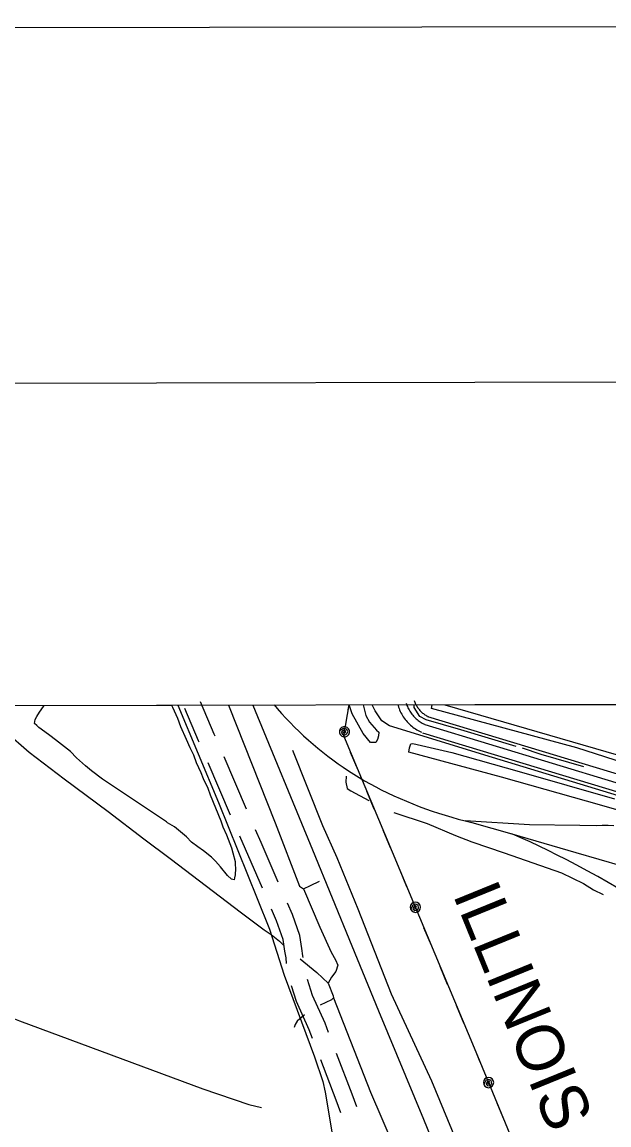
# Model space of a CAD drawing. Extents: x 3324104 to 3361979, y 612876 to 638273.
# Drawn here: x 3355510 to 3356542, y 635751 to 637690 of the extents above; entities that cross this region are included whole.
import ezdxf

# ---------------------------------------------------------------- set-up
doc = ezdxf.new("R2010")
doc.units = 0
for name, color, linetype in [('G-ANNO-NPLT', 7, 'Continuous'), ('V-ANNO-SYMB', 7, 'Continuous'), ('V-GRID-FRAM', 7, 'Continuous'), ('V-RAIL-IDEN', 7, 'Continuous'), ('V-RAIL-TRAK', 7, 'Continuous'), ('V-ROAD-CNTR', 7, 'Continuous'), ('V-SITE-OTLN', 7, 'Continuous'), ('V-SITE-VEGE', 7, 'Continuous'), ('V-TOPO-SHOR', 7, 'Continuous'), ('V-UTIL-LINE', 7, 'Continuous')]:
    doc.layers.add(name, color=color, linetype=linetype)

msp = doc.modelspace()

# ---------------------------------------------------------------- linework, layer by layer
at = {"layer": 'G-ANNO-NPLT'}
msp.add_lwpolyline([(3324729.4, 613459.1), (3361396, 613523.1), (3361353.8, 637689.8), (3324687.2, 637625.8)], close=True, dxfattribs=at)
at = {"layer": 'V-ANNO-SYMB'}
msp.add_lwpolyline([(3327478.4, 614089), (3360561.6, 614146.7), (3360521.6, 637063.3), (3327438.4, 637005.5), (3327478.4, 614089)], dxfattribs=at)
at = {"layer": 'V-GRID-FRAM'}
msp.add_lwpolyline([(3328194.1, 636440.7), (3359767.9, 636495.9), (3359807.6, 618312.1), (3328217.9, 618256.9), (3328194.1, 636440.7)], dxfattribs=at)
at = {"layer": 'V-RAIL-TRAK'}
for points in [[(3355915.7, 636489.1), (3356020.4, 636234.6), (3356089.6, 636065.9), (3356136.8, 635951.6), (3356215.6, 635761.2), (3356284.7, 635591.1)], [(3355953, 636489.2), (3355958.5, 636482.7), (3355965.9, 636474.4), (3355973.4, 636466.2), (3355981.1, 636458.2), (3355988.9, 636450.3), (3355996.8, 636442.5), (3356004.9, 636434.9), (3356013.2, 636427.4), (3356021.6, 636420.1), (3356030.1, 636413), (3356038.7, 636406), (3356047.5, 636399.1), (3356056.4, 636392.5), (3356065.4, 636385.9), (3356074.5, 636379.6), (3356083.8, 636373.4), (3356093.2, 636367.4), (3356102.6, 636361.6), (3356112.2, 636356), (3356121.9, 636350.5), (3356131.7, 636345.2), (3356141.5, 636340.1), (3356152.4, 636334.7), (3356163.3, 636329.6), (3356174.4, 636324.6), (3356185.5, 636319.8), (3356196.7, 636315.3), (3356207.9, 636310.9), (3356219.3, 636306.7), (3356230.7, 636302.7), (3356242.1, 636298.8), (3356253.7, 636295.2), (3356265.3, 636291.8), (3356276.9, 636288.6), (3356288.7, 636285.6), (3356300.4, 636282.7), (3356370.8, 636262.5), (3356483.7, 636230.1), (3356807.1, 636136.2)], [(3356550.7, 636276.9), (3356540.2, 636277.1), (3356529.7, 636277.1), (3356519.2, 636276.8), (3356490.7, 636277.2), (3356402.4, 636278.3), (3356288.7, 636285.6)], [(3356558.7, 636166.5), (3356540.5, 636177), (3356522.2, 636187.4), (3356503.7, 636197.5), (3356485.2, 636207.6), (3356466.6, 636217.4), (3356450.9, 636225.4), (3356435.1, 636233.3), (3356419.2, 636240.9), (3356403.1, 636248.3), (3356387, 636255.5), (3356370.8, 636262.5)]]:
    msp.add_lwpolyline(points, dxfattribs=at)
at = {"layer": 'V-ROAD-CNTR'}
for p, q in [((3355876.5, 636295.4), (3355836.9, 636387.2)), ((3355904.6, 636306.1), (3355865, 636397.9))]:
    msp.add_line(p, q, dxfattribs=at)
for points in [[(3355821.1, 636423.9), (3355820.1, 636426.3), (3355795.8, 636483)], [(3355849.1, 636434.6), (3355847.7, 636438.1), (3355823.4, 636494.8)], [(3356170.9, 636488), (3356171.7, 636485.6), (3356172.6, 636483), (3356173.7, 636480.5), (3356174.8, 636477.9), (3356176, 636475.5), (3356177.3, 636473.1), (3356178.7, 636470.7), (3356180.2, 636468.4), (3356181.8, 636466.1), (3356183.4, 636463.9), (3356185.2, 636461.7), (3356187, 636459.6), (3356188.9, 636457.6), (3356190.8, 636455.7), (3356192.8, 636453.8), (3356194.9, 636452), (3356197.1, 636450.3), (3356199.3, 636448.6), (3356201.5, 636447.1), (3356203.9, 636445.6), (3356206.2, 636444.2), (3356208.7, 636442.9), (3356211.1, 636441.7), (3356212, 636441.3)], [(3356185.1, 636492.6), (3356185.8, 636490.5), (3356186.6, 636488.4), (3356187.4, 636486.4), (3356188.4, 636484.4), (3356189.3, 636482.4), (3356190.4, 636480.4), (3356191.5, 636478.5), (3356192.7, 636476.7), (3356194, 636474.8), (3356195.3, 636473.1), (3356196.7, 636471.3), (3356198.1, 636469.7), (3356199.6, 636468), (3356201.2, 636466.5), (3356202.8, 636465), (3356204.5, 636463.5), (3356206.2, 636462.1), (3356208, 636460.8), (3356209.8, 636459.6), (3356211.7, 636458.4), (3356213.6, 636457.2), (3356215.6, 636456.2), (3356217.6, 636455.2), (3356218.3, 636454.8)], [(3356199.4, 636497.3), (3356200, 636495.4), (3356200.6, 636493.9), (3356201.2, 636492.3), (3356201.9, 636490.8), (3356202.7, 636489.3), (3356203.4, 636487.8), (3356204.3, 636486.4), (3356205.2, 636485), (3356206.2, 636483.6), (3356207.2, 636482.3), (3356208.2, 636481), (3356209.3, 636479.7), (3356210.4, 636478.5), (3356211.6, 636477.3), (3356212.9, 636476.1), (3356214.1, 636475), (3356215.4, 636474), (3356216.8, 636473), (3356218.1, 636472), (3356219.6, 636471.1), (3356221, 636470.3), (3356222.5, 636469.5), (3356224, 636468.7), (3356224.6, 636468.4)], [(3356222.7, 636469.2), (3356670.5, 636333.3), (3357164.2, 636184.8)], [(3356218.3, 636454.8), (3356666.2, 636319), (3357159.9, 636170.5)], [(3356213.9, 636440.5), (3356661.8, 636304.6), (3357155.6, 636156.1)], [(3355960.3, 636177.7), (3355929.9, 636247.3), (3355920.4, 636269.4)], [(3355932.3, 636167), (3355902.4, 636235.4), (3355892.4, 636258.7)], [(3356003.9, 636045.5), (3356003.6, 636048.4), (3356001.6, 636061.3), (3355998.1, 636084.1), (3355985.2, 636120.6), (3355976.3, 636141)], [(3355974.9, 636034.6), (3355973.9, 636044.6), (3355971.9, 636056.6), (3355968.9, 636076.8), (3355957.3, 636109.6), (3355948.3, 636130.3)], [(3356048.6, 635913.6), (3356042.5, 635929.6), (3356020.3, 635978.3), (3356011.9, 636006.4)], [(3356020.6, 635902.9), (3356014.8, 635918), (3355992.1, 635967.8), (3355983.8, 635995.7)], [(3356070.3, 635772), (3356062.1, 635794.4), (3356034.9, 635865.6)], [(3356098.3, 635782.7), (3356090.2, 635804.9), (3356062.9, 635876.3)]]:
    msp.add_lwpolyline(points, dxfattribs=at)
at = {"layer": 'V-SITE-OTLN'}
for p, q in [((3356125.6, 636489.5), (3357284.2, 636491.5)), ((3356130.8, 636478.7), (3356125.6, 636489.5)), ((3356142.6, 636461.2), (3356130.8, 636478.7)), ((3356155.8, 636452.8), (3356142.6, 636461.2)), ((3356337.3, 636396.6), (3356155.8, 636452.8)), ((3356667.1, 636296.2), (3356337.3, 636396.6))]:
    msp.add_line(p, q, dxfattribs=at)
at = {"layer": 'V-SITE-VEGE'}
for p, q in [((3355543.1, 636480.9), (3355548.3, 636488.1)), ((3355548.3, 636488.1), (3355548.6, 636488.5)), ((3355548.6, 636488.5), (3355772.7, 636488.9)), ((3355772.7, 636488.9), (3355774.2, 636485.1)), ((3355774.2, 636485.1), (3355782.9, 636466)), ((3355531.6, 636456.7), (3355532.6, 636463.9)), ((3355532.6, 636463.9), (3355535.8, 636469.1)), ((3355535.8, 636469.1), (3355540.5, 636476.3)), ((3355540.5, 636476.3), (3355543.1, 636480.9)), ((3355782.9, 636466), (3355788.5, 636451.5)), ((3355535.7, 636453.1), (3355531.6, 636456.7)), ((3355539.3, 636449.4), (3355535.7, 636453.1)), ((3355549.6, 636442.1), (3355539.3, 636449.4)), ((3355788.5, 636451.5), (3355798.1, 636429.2)), ((3355558.3, 636435.3), (3355549.6, 636442.1)), ((3355568.6, 636428), (3355558.3, 636435.3)), ((3355594.8, 636407.2), (3355568.6, 636428)), ((3355798.1, 636429.2), (3355804.8, 636414.6)), ((3355605.6, 636396.3), (3355594.8, 636407.2)), ((3355804.8, 636414.6), (3355810.9, 636401.7)), ((3355621, 636382.2), (3355605.6, 636396.3)), ((3355810.9, 636401.7), (3355816, 636388.2)), ((3355816, 636388.2), (3355824.1, 636370.6)), ((3355631.8, 636373.4), (3355621, 636382.2)), ((3355650.9, 636358.8), (3355631.8, 636373.4)), ((3355824.1, 636370.6), (3355828.2, 636360.2)), ((3355763.6, 636283.6), (3355650.9, 636358.8)), ((3355828.2, 636360.2), (3355836.4, 636343.1)), ((3355836.4, 636343.1), (3355840.4, 636331.2)), ((3355840.4, 636331.2), (3355859.2, 636285.6)), ((3355765.7, 636282), (3355763.6, 636283.6)), ((3355777.5, 636274.7), (3355765.7, 636282)), ((3355781.1, 636272.1), (3355777.5, 636274.7)), ((3355798.6, 636257.5), (3355781.1, 636272.1)), ((3355859.2, 636285.6), (3355862.8, 636274.7)), ((3355862.8, 636274.7), (3355869.4, 636260.7)), ((3355807.8, 636248.2), (3355798.6, 636257.5)), ((3355869.4, 636260.7), (3355878.1, 636237.9)), ((3355818.6, 636239.8), (3355807.8, 636248.2)), ((3355828.9, 636232.5), (3355818.6, 636239.8)), ((3355842.8, 636221.6), (3355828.9, 636232.5)), ((3355878.1, 636237.9), (3355880.6, 636229.1)), ((3355850, 636214.8), (3355842.8, 636221.6)), ((3355858.7, 636204.4), (3355850, 636214.8)), ((3355880.6, 636229.1), (3355884.6, 636214.1)), ((3355884.6, 636214.1), (3355884.6, 636208.9)), ((3355871, 636189.3), (3355858.7, 636204.4)), ((3355885.1, 636201.7), (3355884.5, 636190.3)), ((3355884.6, 636208.9), (3355885.1, 636201.7)), ((3355878.2, 636183.1), (3355871, 636189.3)), ((3355882.9, 636181.5), (3355878.2, 636183.1)), ((3355883.4, 636185.1), (3355882.9, 636181.5)), ((3355884.5, 636190.3), (3355883.4, 636185.1))]:
    msp.add_line(p, q, dxfattribs=at)
at = {"layer": 'V-TOPO-SHOR'}
msp.add_line((3356120.5, 636458.9), (3356133, 636444.9), dxfattribs=at)
for points in [[(3355872.5, 636489.1), (3355954.5, 636282.1), (3355997.7, 636170.5), (3356004.6, 636166.2), (3356017.1, 636171.7), (3356032.5, 636179.3)], [(3356133, 636444.9), (3356137.1, 636441.4), (3356136.4, 636435.2), (3356135, 636428.2), (3356132.1, 636423.4), (3356130.1, 636423.4), (3356122.4, 636423.4), (3356109.3, 636438.8), (3356090, 636473.7), (3356084.8, 636489.4)], [(3356109.5, 636489.5), (3356114.4, 636470.8), (3356120.5, 636458.9)], [(3356378.6, 636415.9), (3356281.4, 636445.7), (3356220.3, 636462.8), (3356209.2, 636469.1), (3356199.5, 636484.5), (3356199.1, 636489.6)], [(3355480.7, 636442.4), (3355522.3, 636406.5), (3355583.8, 636359.2), (3355660.9, 636301.8), (3355723.8, 636253.7), (3355770.4, 636219.2)], [(3355985.3, 636409.9), (3356038, 636277.3), (3356063.4, 636220.8), (3356100.4, 636130.8), (3356158.6, 635981.6), (3356230, 635828.7), (3356271.7, 635726.2), (3356348.5, 635542), (3356409.4, 635388.5), (3356468.4, 635253.9), (3356519.8, 635119.9), (3356562.2, 635018.1), (3356611.6, 634907.1), (3356648.7, 634809.9)], [(3356617, 636302.7), (3356637.2, 636297), (3356646.2, 636292.8), (3356651.7, 636288.5), (3356651.7, 636284.4), (3356651.7, 636280.9), (3356646.8, 636279.5), (3356628.7, 636282.4), (3356608.6, 636289.5), (3356529.4, 636312.3), (3356353, 636362.1), (3356189.8, 636406.3), (3356191.2, 636413.9), (3356193.4, 636420.9), (3356196.8, 636421.6), (3356265.6, 636405.8), (3356383.7, 636372.4), (3356551.8, 636324)], [(3356497.4, 636380.3), (3356422.4, 636402.4), (3356389.7, 636413)], [(3356079.6, 636364.1), (3356078.8, 636353.6), (3356081.6, 636342.5), (3356087.8, 636338.3), (3356119.7, 636321.4)], [(3356163.4, 636300.2), (3356222.4, 636281), (3356271.7, 636259.9), (3356300.8, 636248.5), (3356357.8, 636229.4), (3356458.4, 636193.9), (3356497.3, 636175.6), (3356514.6, 636164.4), (3356531.9, 636155.9)], [(3355770.4, 636219.2), (3355895.8, 636123.8), (3355935.2, 636093.6), (3355947.7, 636085.9), (3355962.2, 636074), (3355969.9, 636066.3)], [(3356004.6, 636166.2), (3356033.4, 636098.6), (3356053.3, 636054.6), (3356060.8, 636041.3), (3356065, 636031.6), (3356061.4, 636020.4), (3356053.7, 636010.8), (3356048.1, 636000.4)], [(3355998.9, 636043.1), (3356028, 636018.6), (3356048.1, 636000.4), (3356057, 635978), (3356057.6, 635974.6), (3356054.1, 635971.1), (3356033.9, 635961.5)], [(3356057.6, 635974.6), (3356122.7, 635808.5), (3356185.7, 635661.3), (3356166.2, 635651)], [(3355306.2, 635541.5), (3355270.1, 635565.3), (3355271.6, 635572.4), (3355273.8, 635578.7), (3355290.3, 635599.2), (3355293.9, 635614.8), (3355309.8, 635649.5), (3355319.9, 635672.9), (3355324.3, 635687.8), (3355330.3, 635724.7), (3355341.2, 635768), (3355347.8, 635787.2), (3355359.2, 635801.3), (3355402.4, 635869.9), (3355449.8, 635942.1), (3355456.3, 635947.7), (3355466.2, 635949.1), (3355505.2, 635933.8), (3355630, 635887.4), (3355827.7, 635814.2), (3355908.6, 635786.6), (3355930.5, 635781.5)], [(3356006.6, 635944.3), (3355993.4, 635933.2), (3355989.8, 635927.7), (3355988.4, 635922.1)]]:
    msp.add_lwpolyline(points, dxfattribs=at)
at = {"layer": 'V-UTIL-LINE'}
msp.add_line((3356626.2, 636368.9), (3356485.4, 636413.6), dxfattribs=at)
for points in [[(3355783.8, 636488.9), (3355854.9, 636317.8), (3355923, 636149.2), (3355944.6, 636094.8), (3355970.8, 636014.3), (3356023.9, 635870.5), (3356038.7, 635827.1), (3356042.7, 635808.6), (3356081.5, 635577.7)], [(3359778.1, 631804.5), (3358880.1, 632347.8), (3358382, 632698.4), (3357961.3, 633061.4), (3357548.2, 633517.7), (3357255.4, 633931.7), (3356960.8, 634342.1), (3356736.1, 634811.3), (3356526.7, 635349.8), (3356308.1, 635878.7), (3356075.3, 636434.9), (3356085, 636489.4)], [(3356083.4, 636480.6), (3356085, 636489.4)], [(3356485.4, 636413.6), (3356229.8, 636483), (3356231.1, 636489.7)], [(3356253.1, 636489.7), (3356945.1, 636289.2), (3357051, 636259), (3357117.1, 636491.2)], [(3356076.6, 636442.2), (3356074, 636441), (3356076, 636439.8), (3356078.5, 636441), (3356078.6, 636443.9), (3356075.3, 636444.7), (3356071.4, 636442.1), (3356072.5, 636437.9), (3356076.9, 636435.9), (3356080.8, 636438.3), (3356082.5, 636442.4), (3356080.1, 636446.6), (3356074.8, 636447.9), (3356067.7, 636443.7), (3356067.8, 636440.2), (3356069.2, 636437), (3356071.8, 636434.6), (3356075, 636433.3), (3356078.5, 636433.4), (3356081.8, 636434.8), (3356084.2, 636437.3), (3356085.5, 636440.6), (3356085.4, 636444.1), (3356084, 636447.3), (3356081.4, 636449.7), (3356078.2, 636451), (3356074.7, 636450.9), (3356071.4, 636449.5), (3356069, 636447), (3356067.7, 636443.7)], [(3356100.6, 636374.4), (3356087.5, 636405.7)], [(3356129.2, 636306.1), (3356116.1, 636337.5)], [(3356157.8, 636237.8), (3356144.6, 636269.2)], [(3356186.3, 636169.6), (3356173.2, 636200.9)], [(3356201.4, 636133.6), (3356199.8, 636131.2), (3356202.2, 636131.3), (3356203.6, 636133.6), (3356202.2, 636136.2), (3356199, 636135), (3356197.1, 636130.7), (3356200.2, 636127.8), (3356205.1, 636128.4), (3356207, 636132.6), (3356206.2, 636137), (3356201.9, 636139.2), (3356196.7, 636137.4), (3356193.1, 636130.1), (3356195.1, 636127.2), (3356198, 636125.3), (3356201.4, 636124.6), (3356204.9, 636125.3), (3356207.8, 636127.3), (3356209.7, 636130.2), (3356210.4, 636133.6), (3356209.7, 636137.1), (3356207.7, 636140), (3356204.8, 636141.9), (3356201.4, 636142.6), (3356197.9, 636141.9), (3356195, 636139.9), (3356193.1, 636137), (3356192.4, 636133.6), (3356193.1, 636130.1)], [(3356229.6, 636066.3), (3356216.4, 636097.6)], [(3356258.1, 635998), (3356245, 636029.4)], [(3356286.7, 635929.7), (3356273.6, 635961.1)], [(3356315.2, 635861.4), (3356308.1, 635878.7), (3356302.2, 635892.8)], [(3356330.1, 635825.4), (3356328.5, 635823), (3356330.9, 635823.1), (3356332.3, 635825.4), (3356330.9, 635828), (3356327.7, 635826.8), (3356325.8, 635822.5), (3356328.9, 635819.6), (3356333.7, 635820.2), (3356335.7, 635824.4), (3356334.9, 635828.8), (3356330.7, 635831), (3356325.5, 635829.2), (3356321.8, 635822), (3356323.7, 635819), (3356326.7, 635817.1), (3356330.1, 635816.4), (3356333.5, 635817.1), (3356336.5, 635819), (3356338.4, 635821.9), (3356339.1, 635825.4), (3356338.4, 635828.8), (3356336.5, 635831.8), (3356333.6, 635833.7), (3356330.1, 635834.4), (3356326.7, 635833.7), (3356323.7, 635831.8), (3356321.8, 635828.8), (3356321.1, 635825.4), (3356321.8, 635822)], [(3356358, 635757.9), (3356345, 635789.4)]]:
    msp.add_lwpolyline(points, dxfattribs=at)

# ---------------------------------------------------------------- texts
at = {"layer": 'V-RAIL-IDEN'}
msp.add_text('ILLINOIS', height=83, rotation=292.159, dxfattribs=at).set_placement((3356266.5, 636156.4))

doc.saveas('drawing.dxf')
